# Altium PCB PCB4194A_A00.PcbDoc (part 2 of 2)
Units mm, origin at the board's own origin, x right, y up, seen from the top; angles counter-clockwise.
Board outline 30 x 45 mm, 4 copper layers (Top Layer, Signal Layer 2, Signal Layer 3, Bottom Layer), stack 1.6 mm thick; 81 components, 86 nets, 293 pads, 429 vias.
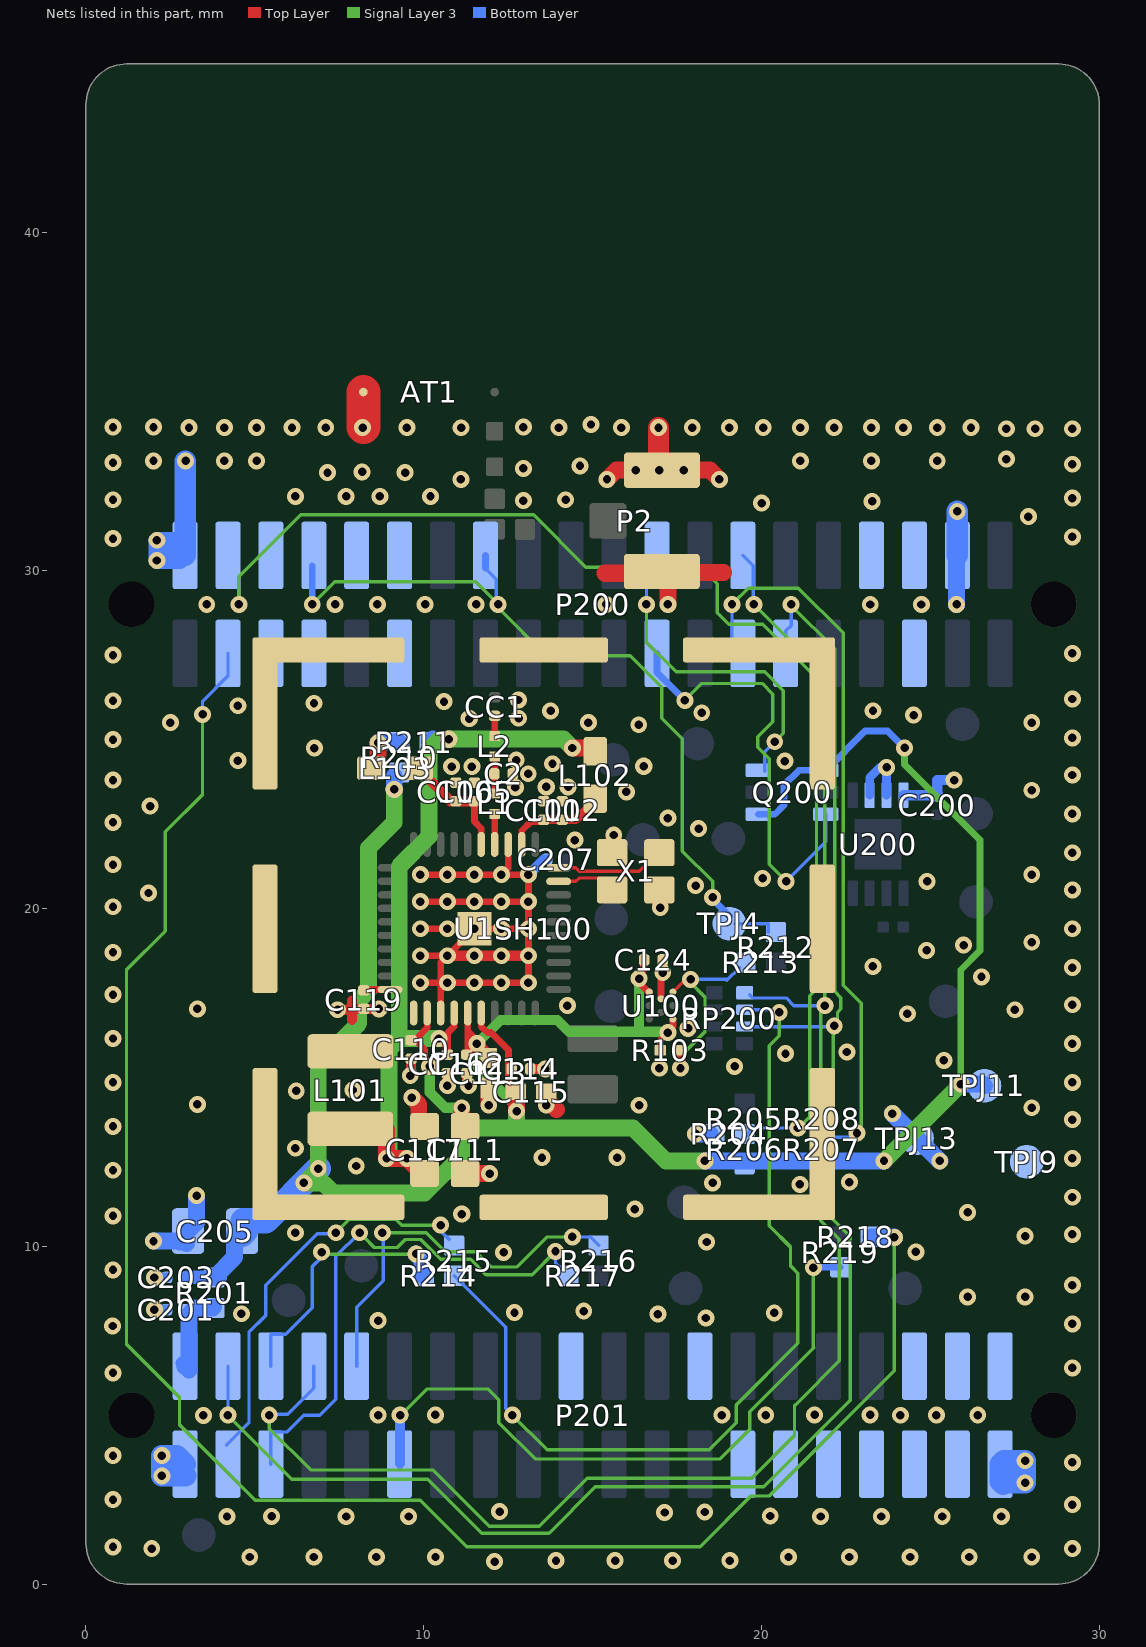
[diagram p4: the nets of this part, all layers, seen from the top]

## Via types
v1: diameter 0.5, hole 0.25, Top Layer to Bottom Layer, tented both sides, 401 vias
v2: diameter 0.508, hole 0.25, Top Layer to Bottom Layer, tented both sides, 28 vias

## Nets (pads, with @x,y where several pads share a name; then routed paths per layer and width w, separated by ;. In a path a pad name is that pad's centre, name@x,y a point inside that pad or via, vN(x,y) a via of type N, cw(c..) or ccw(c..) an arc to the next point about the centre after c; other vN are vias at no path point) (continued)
FLASH_SCS: R103.1 R213.2 U100.A3 | length 6
  Top Layer w0.102: U100.A3@17.375,17.525 U100.A3@17.387,17.537 ; U100.A3@17.4,17.525 17.4,17.55 17.801,17.951 v1@17.974,17.951
  Top Layer w0.3: v1(17.6,15.275) R103.1@17.6,15.775
  Signal Layer 3 w0.102: v1(17.6,15.275) 17.6,15.625 18.325,16.35 18.325,17.375 v1@17.9,17.8 ; v1@17.901,17.801 v1(17.901,17.901)
  Bottom Layer w0.102: v1(17.901,17.901) 18.949,17.901 18.975,17.875 R213.2@19.35,18.25
GND: AT1.2 C2.2 C101.2 C102.2 C105.2 C106.2 C110.2 C111.2 C112.2 C113.2 C114.2 C115.2 C116.2 C117.2 C119.2 C124.2 C200.2 C201.2 C203.2 C205.2 C207.2 P2.2 P2.3 P200.2 P200.38 P201.1 P201.39 R204.2 SH100.1 TPJ13.1 U1.0 U1.13 U1.33 U100.B2 U200.2 U200.3 U200.4 X1.2 X1.4 | length 67.1
  Top Layer w0.2: v1@2.2,3.8 v1@2.225,3.825 ; v1(9.9,17.8) v1@10.5,17.8 ; v1(9.9,18.6) v1(10.7,18.6) ; v1(9.9,19.4) v1(10.7,19.4) v1(11.5,19.4) ; v1(9.9,20.2) v1(10.7,20.2) v1(11.5,20.2) v1(12.3,20.2) v1(13.1,20.2) ; v1(9.9,21) v1(10.7,21) v1(11.5,21) v1(12.3,21) ; U1.33@10.5,16.905 v1@10.5,17.8 ; U1.13@12.5,21.895 12.5,21.2 v1(12.3,21) ; U100.B2@17.025,17.325 17.025,17.925 v1@17.05,17.95 ; v1@10.5,17.8 10.5,18.4 v1(10.7,18.6) ; v1@10.5,17.8 v1(10.7,17.8) v1(11.5,17.8) v1(12.3,17.8) v1(13.1,17.8) v1(13.1,18.6) v1(13.1,19.4) ; v1(10.7,18.6) v1(11.5,19.4) ; v1(11.5,19.4) v1(12.3,19.4) v1(13.1,19.4) ; v1(12.3,21) v1(13.1,21) v1(13.1,20.2) ; v1(13.1,19.4) v1(13.1,20.2)
  Top Layer w0.254: P2.3@16.95,32.85 P2.3@17.075,32.725
  Top Layer w0.3: v1(7.45,17) 7.848,17 7.874,17.026 ; 7.875,16.7 7.875,17.025 ; 7.875,17.275 7.875,17.025 ; v1(8.675,17.025) C119.2@8.225,17.025 7.875,17.025 ; v1(9.6,15.05) 9.6,15.076 9.625,15.101 v1@9.626,15.1 ; v1@9.625,15.15 C110.2@9.625,15.45 ; v1(10.7,14.75) 10.7,14.675 10.725,14.65 10.725,14.775 v1(10.7,14.75) C116.2@10.7,15.075 ; v1(10.7,18.6) v1(11.5,18.6) v1(12.3,18.6) v1(13.1,18.6) ; v1@11.275,14.9 C112.2@11.275,15.1 ; C114.2@13.2,15.25 v1@13.575,15.25 ; C115.2@13.525,14.575 C115.2@13.625,14.575 ; v1@17.05,18.025 17.075,18.05 v1(17.075,18.1) C124.2@17.075,18.475 ; v1@13.575,15.25 13.55,15.225 13.576,15.199 13.6,15.224 v1(13.6,15.25) v1@13.575,15.25
  Top Layer w0.5: v1(9.65,14.4) 9.852,14.198 C117.2@9.852,13.704 ; C111.2@11.225,12.15 v1(11.95,12.15) ; v1(11.925,14.175) C113.2@11.925,14.6 ; v1(13.625,14.175) C115.2@13.625,14.35 ; 13.925,14.05 C115.2@13.625,14.35 ; v1(15.425,32.7) 15.7,32.975 v1(16.275,32.975) P2.3@16.55,32.7 ; v1(15.625,22.175) 15.625,21.825 15.575,21.775 15.675,21.675 X1.2@15.725,21.675 ; X1.4@16.925,20.6 16.9,20.575 17,20.475 v1(17,20.025) ; P2.3@17.15,32.725 17.4,32.975 v1(17.7,32.975) 18.475,32.975 v1(18.75,32.7) ; v1(17.225,29) P2.2@17.225,29.877 ; P2.2@17.499,29.95 18.875,29.95 ; C115.2@13.625,14.35 C115.2@13.625,14.475 ; C115.2@13.625,14.475 13.675,14.525 C115.2@13.625,14.575 C115.2@13.625,14.475
  Top Layer w0.508: 15.375,29.925 P2.2@17,29.925
  Top Layer w0.635: P2.3@16.95,32.85 v1(16.95,34.233)
  Top Layer w1: v1@8.214,34.255 AT1.2@8.214,35.288
  Bottom Layer w0.254: v1(0.8,9.3) v1@0.875,9.3 ; v1@1.95,8.125 v1@2,8.125 ; v1@1.975,9.075 v1(2.025,9.075) C203.2@2.4,9.075 ; v1(2.025,8.125) v1@2,8.125 ; C201.2@2.4,8.125 v1@2,8.125 ; U200.2@23.2,23.35 23.2,23.875 23.5,24.175 v1(23.7,24.175) U200.3@23.7,23.35
  Bottom Layer w0.3: v1(2.025,8.125) C201.2@2.4,8.125 ; v1(2.025,9.075) C203.2@2.4,9.075 ; v1@13.075,20.975 13.55,21.45 C207.2@13.65,21.45
  Bottom Layer w0.305: v1(3.05,34.233) v1@3.05,34.25 ; v1(9.5,34.233) v1@9.5,34.25 ; U200.4@24.2,23.35 25.2,23.35 25.2,23.8 v1(25.7,23.8)
  Bottom Layer w0.5: v1(2,10.15) 2.75,10.15 2.775,10.125 2.85,10.2 C205.2@2.975,10.075 ; P200.2@2.935,30.9 v1(2.1,30.9) 2.1,30.6 ; C205.2@3.025,10.45 3.275,10.7 v1@3.275,11.475 ; v1(18.05,13.325) R204.2@18.476,13.325 ; v1(25.775,29) 25.775,30.43 P200.38@25.795,30.45 ; 2.1,30.6 2.785,30.6 P200.2@2.935,30.45 2.785,30.3 v1(2.1,30.3) 2.1,30.6
  Bottom Layer w0.508: v1(23.875,13.925) TPJ13.1@24.6,13.2 v1(25.275,12.525)
  Bottom Layer w0.635: P201.1@2.9,3.25 2.95,3.2 v1(2.25,3.2) v1(2.25,3.8) 2.685,3.8 P201.1@2.935,3.55 ; P200.2@2.935,30.45 2.935,30.9 v1@2.935,33.235 ; P200.38@25.795,30.45 v1(25.795,31.755) ; P201.39@27.065,3.55 27.165,3.65 v1(27.8,3.65) ; P201.39@27.065,3.55 27.7,3.55 v1(27.8,3.65) ; P201.39@27.065,3.55 27.065,3.035 27.15,2.95 27.2,3 v1(27.8,3) v1(27.8,3.65)
  other v1: 12.098,0.665 13.915,0.693 15.665,0.693 17.365,0.693 19.065,0.693 4.848,0.8 6.748,0.8 8.598,0.8 10.348,0.8 20.798,0.8 22.598,0.8 24.398,0.8 26.148,0.8 27.998,0.8 1.948,1.05 29.2,1.05 0.8,1.1 4.175,2 5.497,2.004 7.7,2 9.55,2 21.75,2 23.55,2 25.35,2 27.1,2 20.256,2.014 17.129,2.118 18.317,2.132 12.247,2.146 29.2,2.35 0.8,2.5 29.2,3.6 0.8,3.8 3.477,4.992 8.65,5 10.344,5.008 18.825,5 20.125,5 21.571,5.007 23.212,5.007 24.109,4.997 25.175,5 26.4,5 0.8,6.25 29.2,6.4 0.786,7.638 29.2,7.7 8.65,7.8 18.35,7.875 4.6,8 16.931,7.989 20.375,8.025 12.686,8.034 14.735,8.08 26.1,8.5 27.8,8.5 29.2,8.85 12.365,9.819 24.569,9.834 18.375,10.125 27.8,10.3 29.2,10.35 6.2,10.4 0.8,10.9 26.1,11 16.25,11.1 29.2,11.45 3.275,11.5 21.137,11.829 18.55,11.875 22.6,11.9 0.8,12.25 8,12.375 29.2,12.6 13.5,12.625 15.725,12.625 6.2,12.9 0.8,13.55 29.2,13.75 28,14.1 16.375,14.175 3.3,14.2 6.225,14.6 7.9,14.625 11.325,14.75 0.8,14.85 29.2,14.85 16.975,15.275 19.2,15.325 25.4,15.5 20.709,15.703 22.525,15.75 29.2,16 0.8,16.15 17.826,16.451 24.318,16.884 27.5,17 3.3,17.025 14.25,17.125 29.2,17.15 0.8,17.45 26.512,17.973 29.2,18.25 23.295,18.285 0.8,18.7 24.885,18.758 25.98,18.915 28,19 29.2,19.4 0.8,20.05 1.852,20.457 29.2,20.55 18.05,20.675 24.9,20.8 20.034,20.891 28,21 0.8,21.3 29.2,21.65 14.475,22.025 18.137,22.366 0.8,22.55 17.225,22.675 29.2,22.8 1.898,23.03 28,23.5 12.713,23.581 0.8,23.8 29.2,23.95 13.094,23.987 13.811,24.284 20.692,24.362 4.5,24.375 12.738,24.394 6.765,24.747 0.8,25 29.2,25.05 16.366,25.437 2.5,25.5 14.875,25.5 28,25.5 12.807,25.63 24.5,25.725 18.231,25.792 23.3,25.851 4.5,26 6.75,26.075 0.8,26.15 12.801,26.172 29.2,26.2 0.8,27.5 29.2,27.55 3.575,29 7.375,29 8.625,29 10.04,29 11.55,29 23.217,28.998 24.73,28.998 0.8,30.95 29.2,31 27.9,31.6 20,32 23.275,32.05 12.95,32.075 0.8,32.1 14.2,32.1 29.2,32.15 6.2,32.2 7.7,32.2 8.7,32.2 10.2,32.2 11.1,32.7 7.15,32.9 9.45,32.9 8.175,32.925 16.975,32.975 12.95,33.025 14.625,33.1 29.2,33.15 0.8,33.2 2,33.25 2.95,33.25 4.1,33.25 5.05,33.25 21.15,33.25 23.25,33.25 25.2,33.25 27.25,33.3 27.25,34.2 28.1,34.2 29.2,34.2 4.1,34.233 5.05,34.233 6.1,34.233 7.1,34.233 8.192,34.233 11.106,34.232 14,34.233 15.85,34.233 17.95,34.233 19.05,34.233 20.05,34.233 21.15,34.233 22.15,34.233 23.25,34.233 24.2,34.233 25.2,34.233 26.2,34.233 0.8,34.25 2,34.25 12.95,34.25 14.951,34.327
  other v2: 11.125,10.95 16,23.45 13.625,23.6 14.275,23.6 10.825,24.2 11.425,24.2 16.515,24.208 11.347,25.622 13.755,25.847 10.6,26.125 15.4,29
N16773989: U1.9 X1.3 | length 1.5
  Top Layer w0.1: U1.9@13.995,20.8 14.5,20.8 14.6,20.9 14.841,20.9 15.4,20.9 X1.3@15.441,20.859
N16774051: U1.10 X1.1 | length 3
  Top Layer w0.1: U1.10@14.192,21.225 14.217,21.2 14.5,21.2 14.6,21.1 15.1,21.1 16.375,21.1 X1.1@16.95,21.675
N16774211: C101.1 C102.1 L102.2 U1.12 | length 2.8
  Top Layer w0.2: U1.12@12.9,21.895 12.9,22.3 13.175,22.575 13.5,22.575 C101.1@13.55,22.625
  Top Layer w0.25: C101.1@13.569,22.606 13.588,22.625 C102.1@14.1,22.625 14.5,22.625 L102.2@14.975,23.1
N16774267: C105.1 C106.1 L103.2 U1.15 | length 3.3
  Top Layer w0.2: C105.1@11.5,23.175 11.5,22.575 11.701,22.374 U1.15@11.7,21.895
  Top Layer w0.3: L103.2@10.125,24.15 10.125,23.85 10.8,23.175 C106.1@10.95,23.175 C105.1@11.5,23.175
N16774345: L1.1 U1.14 | length 0.9
  Top Layer w0.2: U1.14@12.1,21.895 L1.1@12.1,22.798
N16774387: C2.1 L1.2 L2.1 | length 1.1
  Top Layer w0.2: L1.2@12.1,23.398 12.1,24.497 L2.1@12.103,24.5
N16775186: L101.1 U1.31
N16775238: C119.1 U1.30 | length 0.8
  Top Layer w0.2: C119.1@8.2,17.6 U1.30@9.005,17.6
N16778861: R214.1 R215.1 RP200.6 | length 26.4
  Signal Layer 3 w0.102: v1(12.625,5) 13.65,3.975 18.45,3.975 19.25,4.775 19.25,5.3 21.075,7.125 21.075,9.201 20.856,9.42 20.856,9.978 20.223,10.612 20.223,15.933 20.525,16.236 v1@20.525,16.9
  Bottom Layer w0.102: R214.1@10.9,9.125 12.425,7.6 12.425,5.2 v1(12.625,5) ; RP200.6@19.525,17 v1@20.351,17
  other v1: 20.525,16.925
N16787268: CC1.1 L2.2 | length 0.6
  Top Layer w0.2: L2.2@12.103,25.1 CC1.1@12.103,25.698
PAVDD: L103.1 R210.1 R211.2 | length 1.4
  Top Layer w0.5: L103.1@8.409,24.16 8.65,24.401 v1(8.65,24.9)
  Bottom Layer w0.5: v1@8.675,24.925 R210.1@9.275,24.925
TP_TDI: P200.8 P200.16 R212.1 TPJ4.1 | length 23.6
  Signal Layer 3 w0.1: v1(6.7,29) 7.367,29.667 11.533,29.667 v1(12.2,29) 12.2,28.9 13.619,27.481 16.111,27.481 17.05,26.542 17.05,25.628 17.65,25.027 17.65,21.7 18.55,20.8 v1(18.55,20.325)
  Bottom Layer w0.1: P200.16@11.825,30.075 12.15,29.75 12.15,29.016 12.166,29 v1(12.2,29) ; TPJ4.1@19.225,19.55 20.2,19.55 R212.1@20.2,19.3
  Bottom Layer w0.2: v1(6.7,29) P200.8@6.7,30.138 ; P200.16@11.825,30.075 P200.16@11.825,30.45 ; v1(18.55,20.325) 18.55,20.275 TPJ4.1@19.05,19.775
USB_VBUS: P200.35
USB_VREG: P200.36
VDCDC: C116.1 C117.1 L101.2 L102.1 R211.1 U1.34 | length 24.4
  Top Layer w0.2: v1@10.425,16 10.65,16 C116.1@10.65,15.7 ; v1@10.512,16.113 10.9,16.5 U1.34@10.9,16.905 ; C116.1@10.7,15.675 10.7,16.3 10.725,16.325
  Top Layer w0.5: L101.2@8.8,13.55 8.9,13.45 v1(8.9,12.6) v1(9.5,12.6) C117.1@9.888,12.213 ; v1(14.4,24.75) 15.075,24.75 L102.1@15.1,24.725
  Signal Layer 3 w0.5: 9.275,17.375 9.275,21.25 10.15,22.125 10.15,24.7 ; 9.275,16.15 9.275,17.374 ; v1(9.5,12.6) v1(8.9,12.6) 8.975,12.675 8.975,15.825 9.275,16.125 9.275,16.15 v1(10.45,16.15) ; 10.2,24.75 10.456,25.006 ; v2@10.484,25.01 v2(10.738,25.01) 10.74,25.012 11.686,25.012 14.138,25.012 v1(14.4,24.75)
  Bottom Layer w0.5: R211.1@10.175,24.925 10.272,25.022 10.284,25.01 v2(10.738,25.01)
VMCU: C110.1 C111.1 C112.1 C113.1 C114.1 C115.1 C124.1 C203.1 C205.1 Q200.1 Q200.4 R103.2 R201.2 R206.1 R207.1 R210.2 TPJ11.1 U1.32 U1.35 U1.36 U100.A1 U100.E3 | length 82.8
  Top Layer w0.2: C110.1@9.7,16.125 9.758,16.125 9.825,16.192 ; U1.32@10.1,16.905 10.1,16.467 9.825,16.192 ; v1@10.125,15.475 10.025,15.575 10.025,15.825 9.825,16.025 9.825,16.192 ; C112.1@11.275,15.675 11.35,15.75 C113.1@11.7,15.75 ; C112.1@11.3,15.725 11.3,16.375 ; U1.35@11.3,16.905 11.3,16.375 ; U1.36@11.7,16.8 11.7,16.511 11.886,16.325 11.986,16.325 12.505,15.806 C115.1@12.505,14.65 ; C113.1@11.925,15.575 11.925,15.75 11.3,16.375 ; C115.1@12.55,14.625 12.675,14.625 C115.1@12.85,14.45 ; C124.1@16.525,18.45 16.5,18.425 16.5,18.175 16.312,17.988 16.25,17.925 16.65,17.525 U100.A1@16.675,17.525 ; R103.2@17,15.875 17,16.1 v1(17.225,16.325) ; v1@17.15,16.275 17.375,16.5 U100.E3@17.375,16.725
  Top Layer w0.5: C111.1@11.125,13.65 v1(11.125,14.1) ; v1(12.75,14) C115.1@12.75,14.4
  Signal Layer 3 w0.2: v1(24.233,24.751) 24.233,24.264 26.465,22.032 26.465,18.749 25.9,18.184 v1(25.9,14.8)
  Signal Layer 3 w0.3: v1(10.175,15.326) 10.175,14.557 10.632,14.1 v1(11.125,14.1) 11.175,14.1 v1@11.2,14.075 ; v1@11.525,15.975 v1@11.538,15.963 ; v1@12.705,14.17 11.588,15.288 11.588,15.913 v1@11.538,15.963 ; v1(12.75,14) v1@12.75,14.02 ; 16.375,16.5 v2(16.375,17.925) ; v1@17.2,16.3 v1@17.225,16.275 ; v1(17.225,16.325) 17.2,16.35 14.3,16.35 13.95,16.7 12.275,16.7 v1(11.575,16) v1@11.538,15.963
  Signal Layer 3 w0.5: v2@9.125,23.475 9.125,22.55 8.367,21.792 8.367,17.566 8.075,17.274 8.075,16.6 6.875,15.4 v1(6.875,12.3) v1@6.875,12.275 ; v1@11.125,14.075 11.125,13.5 ; v1(12.75,14) 12.75,13.675 12.575,13.5 ; v1(18.325,12.525) 17.175,12.525 16.2,13.5 12.575,13.5 ; v1(23.625,12.525) v1(25.9,14.8) ; 6.876,11.876 6.476,11.876 v1@6.875,12.275 ; 6.876,11.876 6.95,11.95 6.875,12.025 v1@6.875,12.275 ; 6.876,11.876 7.024,11.876 7.325,11.575 10.025,11.575 11.125,12.675 11.125,13.5 ; 11.125,13.5 12.575,13.5
  Bottom Layer w0.2: Q200.1@19.902,22.789 20.394,22.789 20.667,23.062 20.667,23.649 21.107,24.089 Q200.4@21.902,24.089 23.064,25.25 23.734,25.25 v1(24.233,24.751)
  Bottom Layer w0.4: C203.1@3,9.075 R201.2@3.8,9.075
  Bottom Layer w0.5: R201.2@3.775,9.1 R201.2@3.8,9.075 ; R201.2@3.925,9.075 R201.2@3.8,9.075 ; C205.1@4.4,10.225 4.4,9.675 R201.2@3.8,9.075 ; C205.1@4.4,10.35 C205.1@4.625,10.35 ; v2@9.112,23.538 v2@9.125,23.525 ; v2(9.125,23.526) R210.2@9.125,23.925 ; v1(18.325,12.525) v1(23.625,12.525) ; v1(25.9,14.8) 26.55,14.8 TPJ11.1@26.6,14.75
  Bottom Layer w0.75: C205.1@4.625,10.35 4.725,10.45 C205.1@4.625,10.45 ; C205.1@4.65,10.75 5.325,10.75 v1(6.875,12.3)
  other v1: 6.45,11.876
VMCU_IN: C201.1 P201.2 R201.1 | length 2.8
  Bottom Layer w0.4: P201.2@2.85,6.535 2.925,6.46 P201.2@2.935,6.45 ; P201.2@2.925,6.44 P201.2@2.935,6.45 ; P201.2@3.05,6.335 P201.2@2.935,6.45 ; R201.1@3.775,8.15 R201.1@3.8,8.175
  Bottom Layer w0.5: P201.2@2.925,6.44 P201.2@2.925,6.46 ; P201.2@3.05,6.335 3.05,8 3.225,8.175 3.75,8.175 R201.1@3.775,8.2
VRF: TPJ9.1
VRF_IN: P201.40
WSTK_F10: P200.23 Q200.6 | length 13.2
  Signal Layer 3 w0.1: v1(17.732,26.161) 18.232,26.661 20.015,26.661 20.33,26.345 20.33,25.522 19.89,25.082 19.89,24.765 20.227,24.429 20.227,21.308 20.725,20.81 v1(20.725,20.8)
  Bottom Layer w0.1: v1(20.725,20.8) 21.902,21.977 Q200.6@21.902,22.789
  Bottom Layer w0.2: P200.23@16.905,27.55 16.905,26.989 v1(17.732,26.161)
WSTK_F11: P200.24 Q200.3 | length 10
  Signal Layer 3 w0.1: v1(16.593,29.001) 16.593,27.886 17.477,27.002 20.091,27.002 20.647,26.446 20.647,25.192 v1(20.391,24.936)
  Bottom Layer w0.1: v1(16.593,29.001) 16.593,30.138 P200.24@16.905,30.45 ; Q200.3@20.091,24.053 20.091,24.636 v1(20.391,24.936)
WSTK_F14: P200.27 R207.2 R208.2 | length 21.8
  Signal Layer 3 w0.1: v2@19.138,29.012 19.609,29.484 21.091,29.484 22.415,28.16 22.415,17.724 22.95,17.189 22.95,13.375 22.85,13.275 22.825,13.3 v1(22.825,13.35)
  Bottom Layer w0.1: v2@19.125,28.875 19.125,27.87 P200.27@19.445,27.55 ; R207.2@21.775,13.225 22.7,13.225 v1@22.825,13.35
  other v2: 19.125,29
WSTK_F15: P200.28 P201.8 RP200.5 | length 51
  Signal Layer 3 w0.1: v1(5.425,5) 5.425,4.6 6.648,3.377 10.266,3.377 11.934,1.709 13.416,1.709 14.841,3.134 19.704,3.134 20.975,4.404 20.975,5.275 21.1,5.4 22.304,6.604 22.304,10.2 21.75,10.754 21.75,17 v1(21.875,17.125) 21.875,26.9 v1(19.775,29)
  Bottom Layer w0.1: v1(5.425,5) 5.45,5.025 5.975,5.025 6.745,5.795 P201.8@6.745,6.45 ; P200.28@19.445,30.45 19.75,30.145 19.75,29.05 v1@19.725,29.025 ; RP200.5@19.65,17.45 RP200.5@19.687,17.413 ; RP200.5@19.675,17.4 19.725,17.35 20.725,17.35 20.95,17.125 v1(21.875,17.125) v1@22.075,17.125
WSTK_F16: P200.29 P201.4 RP200.7 | length 51.7
  Signal Layer 3 w0.1: v1(4.2,5) 6.092,3.108 10.117,3.108 11.716,1.509 13.709,1.509 15.079,2.879 20.07,2.879 22.63,5.438 22.63,10.281 21.958,10.953 21.958,13.433 22.125,13.6 22.125,16.5 22.151,16.526 22.25,16.623 22.25,16.925 22.35,17.025 22.35,17.363 22.162,17.552 22.162,27.688 v2@20.9,28.95
  Bottom Layer w0.1: v1(4.2,5) 4.2,4.915 4.145,4.97 4.205,5.03 P201.4@4.205,6.45 ; RP200.7@19.6,16.5 v1@22.151,16.5 ; P200.29@20.715,27.55 20.715,28.215 20.875,28.375 20.875,28.875 v2@20.825,28.925
  other v1: 22.151,16.526
  other v2: 20.875,29
WSTK_F21: P200.34
WSTK_P0: P201.3 R215.2 | length 12
  Signal Layer 3 w0.1: v1@7.4,10.226 v1(7.4,10.4) 7.8,10.8 9.175,10.8 9.35,10.625 v1(10.5,10.625)
  Bottom Layer w0.1: P201.3@4.159,4.109 4.825,4.775 4.825,7.45 5.325,7.95 5.325,8.85 6.85,10.375 v1@7.225,10.375 ; v1@7.225,10.4 v1(7.4,10.4) ; v1(10.5,10.625) 10.5,10.45 R215.2@10.75,10.2
WSTK_P2: P201.5 R217.2 | length 16
  Signal Layer 3 w0.1: v1@7.975,10.275 8.225,10.275 8.537,9.963 9.213,9.963 9.45,10.2 9.916,10.2 10.502,9.614 11.386,9.614 11.841,9.159 13.209,9.159 v1(13.9,9.85)
  Bottom Layer w0.1: P201.5@5.475,3.55 5.475,4.5 5.95,4.5 6.45,5 6.925,5 7.4,5.475 7.4,9.7 v1(8.1,10.4) ; v1(13.9,9.85) 13.9,9.5 14.025,9.375 R217.2@14.025,9.225
WSTK_P3: P201.6 R214.2 | length 7.8
  Signal Layer 3 w0.1: v1(6.975,9.825) 7.037,9.763 9.763,9.763 v1(9.775,9.775)
  Bottom Layer w0.1: P201.6@5.475,6.45 5.475,7.375 5.5,7.4 5.919,7.4 6.7,8.181 6.7,9.4 6.975,9.675 v1(6.975,9.825)
  Bottom Layer w0.5: v1(9.775,9.775) 9.95,9.6 9.95,9.175 R214.2@10,9.125
WSTK_P7: P201.10 R216.2 | length 11.4
  Signal Layer 3 w0.1: v1(8.775,10.4) 10.075,10.4 10.633,9.842 11.538,9.842 11.993,9.386 12.761,9.386 13.65,10.275 v1(14.4,10.275)
  Bottom Layer w0.1: P201.10@8.015,6.45 8.015,8.2 8.8,8.985 8.8,10.375 v1(8.775,10.4) ; v1@14.575,10.275 14.925,10.275 R216.2@15.175,10.025
WSTK_P8: P201.11 R219.2 | length 20.3
  Signal Layer 3 w0.1: v1(9.3,5) 9.5,5 9.413,5.088 10.1,5.775 11.9,5.775 12.225,5.45 12.225,4.775 13.297,3.703 18.778,3.703 19.65,4.575 19.65,5.1 21.541,6.991 21.536,6.996 v1(21.536,9.369)
  Bottom Layer w0.1: P201.11@9.285,3.55 P201.11@9.3,3.565 ; v1(21.536,9.369) v1@21.544,9.378
  Bottom Layer w0.2: v1@21.544,9.378 R219.2@22.331,9.378
  Bottom Layer w0.3: P201.11@9.3,3.565 v1(9.3,5)
WSTK_P17: P201.20
WSTK_P23: P201.26
WSTK_P24: P201.27
WSTK_P26: P201.29
WSTK_P28: P201.31
WSTK_P30: P201.33
WSTK_P32: P201.35
WSTK_P33: P201.36
WSTK_P34: P201.37
WSTK_P35: P201.38
WSTK_P36: P200.3 R218.2 | length 54.2
  Signal Layer 3 w0.1: v1(3.451,25.745) 3.451,23.374 2.348,22.271 2.348,19.331 1.2,18.183 1.2,7.101 2.769,5.532 2.769,4.718 5.012,2.475 9.9,2.475 11.268,1.107 18.181,1.107 19.681,2.607 20.229,2.607 23.931,6.308 v1(23.931,10.263)
  Bottom Layer w0.1: v1(3.451,25.745) 3.451,26.138 4.205,26.892 P200.3@4.205,27.55
  Bottom Layer w0.5: R218.2@23.231,10.278 23.916,10.278 v1(23.931,10.263)
WSTK_P37: P200.4 R204.1 R205.2 R206.2 | length 37.3
  Signal Layer 3 w0.1: v1(4.525,29) 4.525,29.819 6.356,31.65 13.25,31.65 14.8,30.1 18.2,30.1 18.687,29.613 18.687,28.757 19.034,28.41 20.04,28.41 21.625,26.825 21.625,17.604 21.431,17.41 21.431,13.831 21.1,13.5 v1(21.075,13.5)
  Bottom Layer w0.1: v1(4.525,29) P200.4@4.525,29.725 ; R206.2@19.5,13.25 19.513,13.238 19.55,13.275 19.55,13.3 19.7,13.45 19.65,13.5 v1(21.075,13.5)
WSTK_P38: P200.5
WSTK_P39: P200.6
WSTK_P40: P200.7
WSTK_P43: P200.10
WSTK_P44: P200.11
WSTK_P45: P200.12
pads on no net: P200.M1 P200.M2 P201.M1 P201.M2 RP200.1 RP200.8 TPJ18.1 TPJ19.1 TPJ20.1 U100.C1 U200.9

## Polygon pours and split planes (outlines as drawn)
GND on Signal Layer 2 "GND_L2" (solid, remove dead copper, pour order 48): 0,0 0,34.6 30,34.6 30,0
GND on Signal Layer 3 "GND_L3" (solid, remove dead copper, pour order 52): 0,0 0,34.6 30,34.6 30,0
GND on Bottom Layer "GND_L4" (solid, remove dead copper, pour order 54): 0,0 0,34.6 30,34.6 30,0
GND on Top Layer "GND_L1" (solid, remove dead copper, pour order 56): 0,0 0,34.6 30,34.6 30,0

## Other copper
Top Layer:
  pour cut-out: 15.45,22.525 15.85,22.525 16.075,22.3 17.575,22.3 17.8,22.075 17.8,20.1 17.375,19.675 14.15,19.675 14.15,21.225
  region net N16775186: 6.7,15.325 6.7,16.25 8.525,16.25 9.575,17.3 9.85,17.3 9.85,16.5 9.5,16.5 9.1,16.1 9.1,15.325
  pour cut-out: 9.25,16.3 14.475,16.3 14.475,15.325 12.8,13.65 9.25,13.65
  pour cut-out: 12.537,25.122 13.484,24.176 13.484,22.186 11.666,22.186 11.666,26.699 12.34,26.699 12.537,26.503
  region net GND: 12.493,24.435 12.493,23.491 12.936,23.491 13.266,23.821 13.266,24.156 12.987,24.435
  region net GND: 10.85,23.55 10.575,23.825 10.575,24.4 11.279,24.4 cw(c11.28,24.109) 11.485,24.315 11.59,24.21 cw(c11.384,24.005) 11.675,24.004 11.675,23.6 cw(c11.625,23.6) 11.625,23.55
  region net GND: 13.375,23.025 13.375,23.525 cw(c13.495,23.525) 13.41,23.61 13.565,23.765 cw(c13.77,23.559) 13.771,23.85 14.525,23.85 14.525,23.325 14.525,23 14.2,23 13.4,23 cw(c13.4,23.025)
Signal Layer 2:
  pour cut-out: 18.252,30.625 18.252,32.325 16.149,32.325 16.149,32.056 14.852,32.055 14.852,30.887 16.148,30.887 16.148,30.625
Bottom Layer:
  pour cut-out: 18.862,15.85 18.862,15.7 19.238,15.7 19.238,15.85
  pour cut-out: 9.53,31.548 9.53,31.367 10.315,31.367 10.315,31.547
  pour cut-out: 8.235,28.65 8.235,28.469 10.292,28.469 10.292,28.646
  pour cut-out: 13.358,31.551 13.357,31.37 14.142,31.37 14.142,31.55
  pour cut-out: 15.89,31.551 15.889,31.369 16.674,31.369 16.674,31.549
  pour cut-out: 17.176,28.638 17.176,28.456 17.96,28.456 17.96,28.636
  pour cut-out: 18.438,31.547 18.437,31.365 19.222,31.365 19.222,31.545
  pour cut-out: 19.716,31.547 19.715,31.365 20.5,31.365 20.5,31.545
  pour cut-out: 20.992,31.549 20.992,31.367 21.777,31.367 21.777,31.547
  pour cut-out: 22.251,28.653 22.251,28.472 23.036,28.472 23.036,28.652
  pour cut-out: 15.922,7.546 15.921,7.365 16.706,7.365 16.706,7.545
  pour cut-out: 14.623,7.55 14.623,7.368 15.408,7.368 15.408,7.548
  pour cut-out: 13.372,7.553 13.372,7.372 14.156,7.372 14.156,7.552
  pour cut-out: 14.568,2.633 14.567,2.451 15.352,2.451 15.352,2.631
  pour cut-out: 13.295,2.636 13.295,2.455 14.08,2.455 14.08,2.635
  pour cut-out: 12.055,2.636 12.055,2.454 12.84,2.454 12.84,2.634
  pour cut-out: 10.793,2.641 10.793,2.46 11.577,2.46 11.577,2.64
  pour cut-out: 9.549,2.638 9.548,2.457 10.333,2.457 10.333,2.636
  pour cut-out: 4.329,2.629 4.329,2.447 7.656,2.447 7.656,2.622
  pour cut-out: 19.715,5.535 19.715,5.353 20.5,5.353 20.5,5.533

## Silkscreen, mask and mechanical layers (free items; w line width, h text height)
Top Overlay:
  text "EFR32xG27" at 1,41 h3.2
  text "2.4 GHz" at 1,39 h1.9
  text "8 dBm, DCDC Buck" at 1,37.5 h1.9
  text "QFN40" at 1,36 h1.9
Bottom Overlay:
  lines w0.15: 1.5,38 1.5,37 2.5,37 ; 1.5,42 1.5,43 2.5,43 ; 19.5,37 20.5,37 20.5,38 ; 19.5,43 20.5,43 20.5,42
  lines w0.152: 8.75,23.825 8.75,23.525 9.05,23.525 ; 8.75,24.725 8.75,24.475 8.85,24.475 ; 8.75,25.125 8.75,25.375 8.85,25.375 ; 9.45,23.525 9.75,23.525 9.75,23.825 ; 9.45,25.4 9.75,25.4 ; 9.5,8.925 9.5,8.625 9.8,8.625 ; 9.5,9.325 9.5,9.625 9.8,9.625 ; 9.75,24.125 9.75,24.425 10.05,24.425 ; 10.1,9.625 10.4,9.625 10.4,9.925 ; 10.35,24.425 10.65,24.425 10.65,24.725 ; 10.35,25.425 10.65,25.425 10.65,25.125 ; 10.4,8.65 10.7,8.65 ; 10.4,10.225 10.4,10.525 10.7,10.525 ; 11.1,10.525 11.4,10.525 11.4,10.225 ; 11.175,8.65 11.4,8.65 11.4,8.925 ; 11.3,9.575 11.4,9.575 11.4,9.325 ; 13.775,8.925 13.775,8.625 14.075,8.625 ; 13.775,9.325 13.775,9.625 14.075,9.625 ; 14.375,9.625 14.675,9.625 14.675,9.925 ; 14.675,8.65 14.975,8.65 ; 14.675,10.225 14.675,10.525 14.975,10.525 ; 15.375,10.525 15.675,10.525 15.675,10.225 ; 15.45,8.65 15.675,8.65 15.675,8.925 ; 15.575,9.575 15.675,9.575 15.675,9.325 ; 18.05,13.125 18.05,12.825 18.35,12.825 ; 18.05,13.525 18.05,13.825 18.35,13.825 ; 18.65,12.825 18.95,12.825 18.95,12.525 ; 18.65,13.825 18.95,13.825 18.95,14.125 ; 18.95,12.225 18.95,11.925 19.25,11.925 ; 18.95,14.425 18.95,14.725 19.25,14.725 ; 19.025,18.2 19.025,17.9 19.325,17.9 ; 19.025,18.6 19.025,18.9 19.325,18.9 ; 19.625,18.9 19.925,18.9 19.925,19.2 ; 19.675,11.925 19.975,11.925 19.975,12.225 ; 19.675,14.725 19.975,14.725 19.975,14.425 ; 19.875,12.875 19.975,12.875 19.975,13.125 ; 19.875,13.775 19.975,13.775 19.975,13.525 ; 19.925,17.925 20.225,17.925 ; 19.925,19.5 19.925,19.8 20.225,19.8 ; 20.625,19.8 20.925,19.8 20.925,19.5 ; 20.825,17.95 20.925,17.95 20.925,18.2 ; 20.825,18.85 20.925,18.85 20.925,18.6 ; 21.275,12.2 21.275,11.9 21.575,11.9 ; 21.275,14.475 21.275,14.775 21.575,14.775 ; 21.795,9.214 21.795,8.914 22.095,8.914 ; 21.795,10.114 21.795,9.864 21.895,9.864 ; 21.795,10.514 21.795,10.764 21.895,10.764 ; 21.925,11.9 22.225,11.9 22.225,12.2 ; 21.925,14.775 22.225,14.775 22.225,14.475 ; 22.495,8.914 22.795,8.914 22.795,9.214 ; 22.495,10.789 22.795,10.789 ; 22.795,9.514 22.795,9.814 23.095,9.814 ; 23.395,9.814 23.695,9.814 23.695,10.114 ; 23.395,10.814 23.695,10.814 23.695,10.514
  text "BOARD INFO" at 20.55,43.35 h1.6
  text "VDCDC" at 14.85,24.525 h1.2
  text "PAVDD / Config." at 6.125,21.24 h1.6 r270
  text "VMCU" at 8.925,19.975 h1.2 r270
  text "DBG / TDI" at 19.544,19.904 h1.2 r270
  text "FLASH_SCS" at 18.25,18.025 h1.2 r315
  text "PA04" at 21.385,17.936 h1.6 r270
  text "PC07" at 21.375,15.025 h1.2 r270
  text "PC07" at 20,14.875 h1.2
  text "PCB4194A Rev. A00" at 28,13.7 h1.52 r270
  text "OFF" at 17.85,13 h1.2
  text "Disp Enable" at 22.923,11.626 h1.6 r270
  text "ON" at 22.751,11.02 h1.2
  text "EXP3" at 10.5,10.95 h1.2 r270
  text "EXP10" at 14.775,10.95 h1.2 r270
  text "ON" at 19.1,10.075 h1.2 r270
  text "JOYSTICK" at 29.079,9.969 h1.2
  text "PD03" at 28.977,8.701 h1.6
  text "Sensor Enable" at 19.85,8.2 h1.6 r270
  text "PC01" at 11.725,8 h1.6 r270
  text "PC03" at 15.925,8 h1.6 r270
  text "EXP11" at 23.706,7.844 h1.2
  text "EXP5" at 15.65,7.725 h1.2
  text "EXP6" at 11.325,7.675 h1.2
Top Solder:
  the board outline again, w1
Bottom Solder:
  the board outline again, w1
BOARD OUTLINE 1:
  the board outline again, w0.1
Mechanical 2:
  lines w0.1: -0.5,0 0.5,0 ; 0,-0.5 0,0.5
Mechanical 11:
  the board outline again, w0.1
Mechanical 12:
  the board outline again, w0.1
Mechanical 26:
  lines w0.2: -125.405,-47.962 -120.405,-47.962 ; -125.405,-0.962 -120.405,-0.962 ; -125.393,46.038 -120.405,46.038 ; -54.197,-94.993 -54.197,-89.993 ; -54.197,90.007 -54.197,95.007 ; 17.103,-94.993 17.103,-89.993 ; 17.103,90.007 17.103,95.007 ; 88.303,-94.993 88.303,-89.993 ; 88.303,90.007 88.303,95.007 ; 154.595,-47.962 159.595,-47.962 ; 154.595,-0.962 159.595,-0.962 ; 154.595,46.038 159.583,46.038 ; -125.393,-94.993 -125.393,94.999 159.595,94.999 159.595,-94.993 -125.393,-94.993 ; -120.405,-89.993 -120.405,90.007 154.595,90.007 154.595,-89.993 -120.405,-89.993
  text "1" at -92.505,91.578 h1.52
  text "2" at -20.197,91.578 h1.52
  text "3" at 52.403,91.578 h1.52
  text "4" at 123.203,91.578 h1.52
  text "D" at 156.593,72.438 h1.52
  text "D" at -123.518,71.233 h1.52
  text "C" at -123.518,23.738 h1.52
  text "C" at 156.466,23.738 h1.52
  text "B" at -123.518,-23.862 h1.52
  text "B" at 156.466,-23.862 h1.52
  text "A" at -123.518,-71.362 h1.52
  text "A" at 156.466,-71.362 h1.52
  text "1" at -91.285,-93.435 h1.52
  text "2" at -20.197,-93.435 h1.52
  text "3" at 52.103,-93.435 h1.52
  text "4" at 122.803,-93.435 h1.52
Mechanical 27:
  circle w0.152: c70.608,-82.839 r1.778
  circle w0.152: c70.608,-82.839 r0.762
  lines w0.152: 59.609,-82.839 66.975,-82.839 ; 68.322,-82.839 72.894,-82.839 ; 60.371,-83.601 60.371,-82.077 66.213,-81.061 66.188,-84.617 60.371,-83.601
  lines w0.2: 34.575,-89.95 34.575,-77.425 ; 34.575,-77.369 74.589,-77.369 ; 34.589,-86.369 74.589,-86.369 ; 54.869,-86.322 54.869,-77.407 ; 134.589,-89.98 134.589,-86.369 ; 144.589,-86.369 144.589,-77.369 ; 154.589,-86.369 74.589,-86.369 ; 154.589,-77.369 74.589,-77.369 ; 74.589,-86.369 74.589,-77.369
  text "SIZE" at 36.589,-79.369 h1.52
  text "DOC NO" at 76.589,-79.369 h1.52
  text "REV" at 146.589,-79.369 h1.52
  text "PROJECTION" at 55.885,-79.718 h1.52
  text ".BoardRevision" at 146.309,-84.29 h2.54
  text "A4" at 39.239,-84.744 h2.54
  text ".BoardName" at 79.088,-84.744 h2.54
  text "REF" at 36.589,-88.369 h1.52
  text "SHEET" at 135.589,-88.369 h1.52
  text "1 of 2" at 145.43,-89.406 h1.52
Mechanical 28:
  lines w0.2: -125.404,-47.963 -120.404,-47.963 ; -125.404,-0.963 -120.404,-0.963 ; -125.392,46.037 -120.404,46.037 ; 154.596,-47.963 159.596,-47.963 ; 154.596,46.037 159.596,46.037
  lines w0.203: -120.429,-89.995 -120.429,90.005 ; -120.404,-89.995 154.596,-89.995 154.596,90.005 -120.404,90.005 ; -54.196,-94.995 -54.196,-89.995 ; -54.196,90.005 -54.196,95.005 ; 17.104,-94.995 17.104,-89.995 ; 17.104,90.005 17.104,95.005 ; 88.304,-94.995 88.304,-89.995 ; 88.304,90.005 88.304,95.005 ; -125.392,-94.995 -125.392,94.997 159.596,94.997 159.596,-94.995 -125.392,-94.995
  text "4" at -91.487,91.577 h1.52
  text "3" at -19.18,91.577 h1.52
  text "2" at 53.42,91.577 h1.52
  text "1" at 124.22,91.577 h1.52
  text "D" at 157.61,72.437 h1.52
  text "D" at -122.501,71.232 h1.52
  text "C" at -122.501,23.737 h1.52
  text "C" at 157.61,22.137 h1.52
  text "B" at -122.501,-23.863 h1.52
  text "B" at 157.61,-24.963 h1.52
  text "A" at 156.592,-71.287 h1.52
  text "A" at -122.501,-71.363 h1.52
  text "A" at 157.483,-71.363 h1.52
  text "4" at -90.268,-93.437 h1.52
  text "3" at -19.18,-93.437 h1.52
  text "2" at 52.967,-93.437 h1.52
  text "1" at 123.82,-93.437 h1.52
Mechanical 29:
  circle w0.152: c-36.426,-82.828 r1.778
  circle w0.152: c-36.426,-82.828 r0.762
  lines w0.152: -38.712,-82.828 -34.14,-82.828 ; -32.794,-82.828 -25.428,-82.828 ; -32.032,-81.05 -26.19,-82.066 -26.19,-83.59 -32.006,-84.606 -32.032,-81.05
  lines w0.2: -120.407,-86.359 -40.407,-86.359 ; -120.407,-77.359 -40.407,-77.359 ; -110.407,-86.359 -110.407,-77.359 ; -100.407,-89.969 -100.407,-86.359 ; -20.687,-86.311 -20.687,-77.396 ; -0.407,-86.359 -40.407,-86.359 ; -0.407,-77.359 -40.407,-77.359 ; -0.393,-89.518 -0.393,-77.4 ; -40.407,-86.359 -40.407,-77.359
  text "REV" at -112.407,-79.359 h1.52
  text "DOC NO" at -42.407,-79.359 h1.52
  text "SIZE" at -2.407,-79.359 h1.52
  text "PROJECTION" at -21.703,-79.707 h1.52
  text ".BoardRevision" at -112.127,-84.279 h2.54
  text ".BoardName" at -44.906,-84.733 h2.54
  text "A4" at -5.057,-84.733 h2.54
  text "SHEET" at -101.407,-88.359 h1.52
  text "REF" at -2.407,-88.359 h1.52
  text "2 of 2" at -111.095,-89.331 h1.52
Mechanical 30:
  lines w0.2: 34.575,-77.369 34.575,-56.53 154.575,-56.53 ; 34.575,-73.434 74.575,-73.434 ; 34.575,-69.434 74.575,-69.434 ; 34.575,-65.434 74.575,-65.434 ; 74.575,-69.435 154.575,-69.435 ; 74.575,-61.434 154.575,-61.434 ; 74.581,-77.369 74.581,-56.53 ; 74.581,-56.519 74.581,-51.3 154.625,-51.3
  text "BRD4182A: EFR32xG22 2.4 GHz 6 dBm" at 75.675,-54.575 h1.8
  text "CUSTOMER" at 75.683,-58.446 h1.27
  text "PROJECT NO" at 36.059,-59.462 h1.52
  text "SILICON LABS" at 93.125,-60.3 h2.5
  text "DRAWING TITLE" at 75.912,-63.374 h1.52
  text "BRD4182" at 36,-64.3 h2.1
  text "DATE" at 36.059,-67.59 h1.52
  text "EFR32xG22 2.4 GHz 6 dBm Radio Board" at 75.825,-67.625 h1.8
  text "'.Print_Date'" at 54.347,-68.606 h1.52
  text "SHEET NAME" at 75.709,-71.527 h1.52
  text "DRAWN" at 36.059,-71.654 h1.52
  text "CHECK" at 36.059,-75.718 h1.52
